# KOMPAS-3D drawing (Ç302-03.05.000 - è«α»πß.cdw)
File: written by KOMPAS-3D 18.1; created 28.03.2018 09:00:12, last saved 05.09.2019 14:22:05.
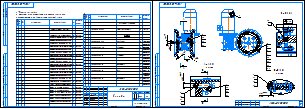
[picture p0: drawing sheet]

Sheets 1-2: A3, landscape

Document properties: Автор: Милов; Полное имя файла: ..\3Д ПВХ\А302-01.05.000 - Корпус.a3d; Масса: 33.4594; Форматы листов документа: 2xA3

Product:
- Part/product: (unnamed)
  - Component: Подшипник 80х40х18 6208-2RS1 SKF  | pos. 21  | Раздел спецификации: Стандартные изделия
  - Component: Шайба C.8.21 ГОСТ 11371-78  | pos. 20  | Раздел спецификации: Стандартные изделия; Примечание: Нерж.
  - Component: Шайба C.5.21 ГОСТ 11371-78  | pos. 19  | Раздел спецификации: Стандартные изделия; Примечание: Нерж.
  - Component: Шайба C 8 ГОСТ 6958-78  | pos. 18  | Раздел спецификации: Стандартные изделия; Примечание: Нерж.
  - Component: Шайба 8 ГОСТ 6402-70  | pos. 17  | Раздел спецификации: Стандартные изделия; Примечание: Нерж.
  - Component: Шайба 5 ГОСТ 6402-70  | pos. 16  | Раздел спецификации: Стандартные изделия; Примечание: Нерж.
  - Component: Кольцо A40.65Г ГОСТ 13942-86  | pos. 15  | Раздел спецификации: Стандартные изделия
  - Component: Гайка М8-6H ГОСТ 5915-70  | pos. 14  | Раздел спецификации: Стандартные изделия; Примечание: Нерж.
  - Component: Винт с цилиндрической головкой. / и шестигранным углублением под ключ / ГОСТ Р ИСО 4762-М8 x 45  | pos. 13  | Раздел спецификации: Стандартные изделия; Примечание: Нерж.
  - Component: Винт с цилиндрической головкой. / и шестигранным углублением под ключ / ГОСТ Р ИСО 4762-М8 x 35  | pos. 12  | Раздел спецификации: Стандартные изделия; Примечание: Нерж.
  - Component: Винт с цилиндрической головкой. / и шестигранным углублением под ключ / ГОСТ Р ИСО 4762-М5 x 16  | pos. 11  | Раздел спецификации: Стандартные изделия; Примечание: Нерж.
  - Component: Винт с цилиндрической головкой. / и шестигранным углублением под ключ / ГОСТ Р ИСО 4762-М5 x 12  | pos. 10  | Раздел спецификации: Стандартные изделия; Примечание: Нерж.
  - Component: Винт с потайной головкой / и шестигранным углублением под ключ / ГОСТ Р ИСО 10642-М4 x 20  | pos. 9  | Раздел спецификации: Стандартные изделия; Примечание: Нерж.
  - Component: Болт М8-6gx30 ГОСТ 7805-70  | pos. 8  | Раздел спецификации: Стандартные изделия; Примечание: Нерж.
  - Component: Фиксатор  | designation А302-01.05.015  | pos. 7  | Раздел спецификации: Детали; Форматы листов документа: А4; Примечание: Сталь 40  / ГОСТ 1050-2013 / Стержень @2~20
  - Component: Упор  | designation А302-01.05.014  | pos. 6  | Раздел спецификации: Детали; Форматы листов документа: А3; Примечание: Сталь 20 / ГОСТ 1050-2013 / Лист 25
  - Component: Фиксатор  | designation А302-01.05.012  | pos. 5  | Раздел спецификации: Детали; Форматы листов документа: А3; Примечание: Д16Т ГОСТ 4784-97 / Плита 20
  - Component: Ловитель  | designation А302-01.05.011  | pos. 4  | Раздел спецификации: Детали; Форматы листов документа: А4; Примечание: Сталь 40  / ГОСТ 1050-2013 / Стержень @2~10
  - Component: Ловитель  | designation А302-01.05.002  | pos. 3  | Раздел спецификации: Детали; Форматы листов документа: А3; Примечание: Фторопласт-4  / ГОСТ 10007-80 Е / Стержень @2~50
  - Component: Основание  | designation А302-03.05.001  | pos. 2  | Раздел спецификации: Детали; Форматы листов документа: А3; Примечание: Полипропилен / Стержень @2~300
  - Component: Мотор-редуктор  | designation А302-02.20.000  | pos. 1  | Раздел спецификации: Сборочные единицы; Форматы листов документа: 2xA3; Примечание: *)2xA3

Title block, sheet 1: Наименование: Корпус; designation: А302-03.05.000; Масса: 33,46; scale: 1:4; sheet number: 1; Количество листов документа: 2; organisation: АО «Астерион»; Форматы листов документа: A3; stored path: Z:\Мембранные насосы\Мембранный электропривод\А302-00.00.000 - ASTRA-302 (МЭ200)\Чертежи\А302-00.05.000 - Корпус.cdw; Разработал: Лифлянд; Проверил: Борисенко; Т. контр.: Лучихин; Утвердил: Григорьева
Title block, sheet 2: sheet number: 2; stored path: Z:\Мембранные насосы\Мембранный электропривод\А302-00.00.000 - ASTRA-302 (МЭ200)\3Д ПВХ\А302-01.05.000 - Корпус.cdw

Views: Разрез А-А, Разрез Б-Б, Разрез В-В
Referenced files in \\192.168.87.28\Konstructor_doc\Мембранные насосы\Мембранный электропривод\А302-00.00.000 - ASTRA-302 (МЭ200)\3Д ПВХ\Отработка\: А302-01.20.000 - Мотор-редуктор.a3d, А302-01.05.002 - Ловитель.m3d, Упор-1.m3d, А302-01.05.000 - Корпус.a3d, Фиксатор.m3d
Referenced files in Z:\Мембранные насосы\Мембранный электропривод\А302-00.00.000 - ASTRA-302 (МЭ200)\3Д ПВХ\: А302-01.20.000 - Мотор-редуктор.cdw
Referenced files in \\192.168.87.28\Konstructor_doc\Мембранные насосы\Мембранный электропривод\А302-00.00.000 - ASTRA-302 (МЭ200)\3Д ПВХ\: А302-01.05.002 - Ловитель.cdw, А302-01.05.001 - Основание.m3d, А302-01.05.001 - Основание.cdw, А302-01.05.012 - Фиксатор.m3d, А302-01.05.012 - Фиксатор.cdw, А302-01.05.014 - Упор.cdw, А302-01.05.011 - Ловитель.m3d, А302-01.05.011 - Ловитель.cdw, А302-01.05.015 - Фиксатор.m3d, А302-01.05.015 - Фиксатор.cdw, А302-01.20.002 - Эксцентрик.m3d
Referenced files in \\192.168.87.28\Konstructor_doc\1 ПКИ 3D\1 Крепеж стандартный\Подшипник\: Подшипник 80х40х18 6208-2RS1 SKF.m3d, Подшипник 52х25х15 62052RSH SKF.m3d
Referenced files in D:\Мембранные насосы\Мембранный электропривод\А302-00.00.000 - ASTRA-302 (МЭ200)\3Д ПВХ\Отработка\: А302-01.20.000 - Мотор-редуктор.a3d, А302-01.05.002 - Ловитель.m3d, Фиксатор.m3d, Упор-1.m3d
Referenced files in D:\1 ПКИ 3D\Двигатели\АИР\: Электродвигатель АИР 80А4 IM 3081 1,1кВт 1400 об..m3d
Referenced files in D:\1 ПКИ 3D\Редуктора NMRW\Редукторы\: Редуктор NMRW 063.m3d, Червячный мотор-редуктор NMRV063 АИР80.a3d
Referenced files in D:\Мембранные насосы\Мембранный электропривод\А302-00.00.000 - ASTRA-302 (МЭ200)\3Д ПВХ\: А302-01.20.001 - Основание.m3d, А302-01.35.000 - Фланец.a3d, А302-01.20.002 - Эксцентрик.m3d, А302-01.05.011 - Ловитель.m3d, А302-01.05.015 - Фиксатор.m3d, А302-01.05.000 - Корпус.a3d
Referenced files in D:\Мембранные насосы\Мембранный электропривод\А302-00.00.000 - ASTRA-302 (МЭ200)\3Д\: А302-00.35.002 - Пластина.m3d, А302-00.35.001 - Труба 140х140х4.m3d, А302-00.20.004 - Вал.m3d, А302-00.20.003 - Ползун.m3d, А302-00.05.001 - Основание.m3d
Referenced files in C:\Program Files\ASCON\KOMPAS-3D v18\Libs\PartLib\DATA\VAULT\methods\kompas\3d\: PLib_Check_spring_rings_GOST_13942_911.m3d, PLib_Washer_1_712.m3d, PLib_Bolt_1_900.m3d, PLib_Washer_2_712.m3d, PLib_Nut_OST92_900.m3d, PLib_Screw_DIN_7984_1500.m3d, PLib_Key_prismatic_712.m3d, PLib_Screw_ISO_10642_1500.m3d
Referenced files in D:\1 ПКИ 3D\1 Крепеж стандартный\Подшипник\: Подшипник 52х25х15 62052RSH SKF.m3d, Подшипник 80х40х18 6208-2RS1 SKF.m3d
Referenced files in C:\Program Files\ASCON\KOMPAS-3D V16\Libs\PartLib\DATA\VAULT\Methods\kompas\3d\: PLib_Bolt_1_900.m3d
Referenced files in Z:\Мембранные насосы\Мембранный электропривод\А302-00.00.000 - ASTRA-302 (МЭ200)\3Д\: А302-00.20.002 - Эксцентрик.m3d
Referenced files in C:\Program Files\ASCON\KOMPAS-3D V16\Libs\PartLib\DATA\vault\Methods\Kompas\3D\: PLib_Check_spring_rings_GOST_13942_911.m3d, PLib_Washer_2_712.m3d, PLib_Washer_1_712.m3d, PLib_Screw_DIN_7984_1500.m3d
Referenced files in \\192.168.87.28\Konstructor_doc\Мембранные насосы\Мембранный электропривод\А302-00.00.000 - ASTRA-302 (МЭ200)\3Д\: А302-00.20.004 - Вал.m3d, А302-00.35.001 - Труба 140х140х4.m3d, А302-00.35.002 - Пластина.m3d, А302-00.20.003 - Ползун.m3d
Referenced files in \\192.168.87.28\Konstructor_doc\1 ПКИ 3D\Двигатели\АИР\: Электродвигатель АИР 80А4 IM 3081 1,1кВт 1400 об..m3d
Referenced files in \\192.168.87.28\Konstructor_doc\1 ПКИ 3D\Редуктора NMRW\Редукторы\: Редуктор NMRW 063.m3d
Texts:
  Мотор-редуктор
  @100~)2xA3
  Ловитель
  Основание
  Шайба C.8.21 ГОСТ 11371-78
  Крепежное изделие ГОСТ
  Шайба
  ГОСТ
  нерж.
  Сталь 12Х18Н10Т ГОСТ 5632-72
  Шайба C 8 ГОСТ 6958-78
  Сталь 20 ГОСТ 1050-2013
  Шайба C 8.04.019 ГОСТ 6958-78
  Шайба 8 ГОСТ 6402-70
  Сталь 30Х13 ГОСТ 5632-72
  Шайба 8 30Х13 019 ГОСТ 6402-70
  Болт М8-6gx30 ГОСТ 7805-70
  Болт
  Болт М8-6gx30.58.019 ГОСТ 7805-70
  Гайка М8-6H ГОСТ 5915-70
  Гайка
  Гайка М8-6H.5.019 ГОСТ 5915-70
  Подшипник 80х40х18 6208-2RS1 SKF
  Подшипник
  SKF
  Фиксатор
  Упор
  Шайба C.5.21 ГОСТ 11371-78
  Шайба 5 ГОСТ 6402-70
  Винт с цилиндрической головкой
  и шестигранным углублением под ключ
  ГОСТ Р ИСО  4762-М5 x 16
  Винт с цилиндрической головкой и шестигранным углублением под ключ
  Р ИСО
  Сталь
  Шайба 5 30Х13 019 ГОСТ 6402-70
  Винт с цилиндрической головкой и шестигранным углублением под ключ ГОСТ Р ИСО  4762-М5 x 16-6.8-A9J
  ГОСТ Р ИСО  4762-М5 x 12
  Винт с цилиндрической головкой и шестигранным углублением под ключ ГОСТ Р ИСО  4762-М5 x 12-6.8-A9J
  Винт с потайной головкой
  ГОСТ Р ИСО  10642-М4 x 20
  Винт с потайной головкой и шестигранным углублением под ключ
  Винт с потайной головкой и шестигранным углублением под ключ ГОСТ Р ИСО  10642-М4 x 20-8.8-A3J
  ГОСТ Р ИСО  4762-М8 x 45
  Винт с цилиндрической головкой и шестигранным углублением под ключ ГОСТ Р ИСО  4762-М8 x 45-6.8-A9J
  ГОСТ Р ИСО  4762-М8 x 35
  Винт с цилиндрической головкой и шестигранным углублением под ключ ГОСТ Р ИСО  4762-М8 x 35-6.8-A9J
  Кольцо A40.65Г ГОСТ 13942-86
  Кольцо
  Сталь 65Г ГОСТ 14959-79
  Винт
  потайной
  головкой
  шестигранным
  углублением
  под
  ключ
  ИСО
  цилиндрической
  *)2xA3
  Полипропилен
  Стержень  300
  Полипропилен / Стержень @2~300
  Фторопласт-4
  ГОСТ 10007-80 Е
  Стержень  50
  Фторопласт-4  / ГОСТ 10007-80 Е / Стержень @2~50
  Сталь 40
  ГОСТ 1050-2013
  Стержень  10
  Сталь 40  / ГОСТ 1050-2013 / Стержень @2~10
  Д16Т ГОСТ 4784-97
  Плита 20
  Д16Т ГОСТ 4784-97 / Плита 20
  Сталь 20
  Лист 25
  Сталь 20 / ГОСТ 1050-2013 / Лист 25
  Стержень  20
  Сталь 40  / ГОСТ 1050-2013 / Стержень @2~20
  Нерж.
  ГОСТ Р ИСО 10642-М4 x 20
  Винт с цилиндрической головкой.
  ГОСТ Р ИСО 4762-М5 x 12
  ГОСТ Р ИСО 4762-М5 x 16
  ГОСТ Р ИСО 4762-М8 x 35
  ГОСТ Р ИСО 4762-М8 x 45
  Электродвигатель / АИР 80А4 IM 3081 1,1кВт 1400 об/мин
  Редуктор NMRW 063
  Мотор-редуктор / NMRV063 N P(кВт) V5 / P(мощн./дв.), i(передат. отн.) см. заказ
  Пластина
  Труба 140х140х4
  Фланец
  Эксцентрик
  Кольцо A25.65Г ГОСТ 13942-86
  Подшипник 52х25х15 62052RSH SKF
  Вал
  Ползун
  Шайба C.5.04.019 ГОСТ 11371-78
  Болт М5-6gx35.58.019 ГОСТ 7805-70
  Гайка М5-6H.5.019 ГОСТ 5915-70
  Винт с цилиндрической головкой и шестигранным углублением под ключ ГОСТ Р ИСО 4762 - М8 x 25 - A2-70
  Винт с цилиндрической головкой и шестигранным углублением под ключ ГОСТ Р ИСО 4762 - М8 x 35 - A2-70
  Гайка М8-6H.21.12Х18Н10Т ГОСТ 5915-70
  Шпонка 8x7x90 ГОСТ 23360-78
Dimensions and other numbers on the sheet: 4; 1; 3; 2; 20; 21; 40Х; 019; 18; 8; 04; 17; 58; 30Х13; 14; 5; 6; 19; 16; 11; 6.8; 10; 9; 8.8; 13; 12; 15; 65Г; 7; 34; 0; 46; 42; 54; 49; 44; 30; 31; 40; 51; 53; 41; 22; 1:4; 33,46

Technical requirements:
  *Размеры для справок.
  Фиксатор поз.5 установить по месту см. разрез В-В.
  Винт потай М4 поз.9 стопорить краской в резьбу.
